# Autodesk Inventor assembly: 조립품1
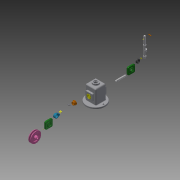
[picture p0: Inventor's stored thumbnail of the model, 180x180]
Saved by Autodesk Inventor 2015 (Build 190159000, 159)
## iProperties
Created: 2021-08
Part Number: 조립품1
Document SubType Name: Assembly
Designer: 104658
Author: 104658
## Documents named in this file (16)
- C:\Users\104658\Desktop\710806V1022\조립품1.iam
- C:\Users\104658\Desktop\710806V1022\V벨트풀리.ipt
- C:\Users\104658\Desktop\710806V1022\고정핀 1.2x8.ipt
- C:\Users\104658\Desktop\710806V1022\뒤커버.ipt
- C:\Users\104658\Desktop\710806V1022\링크.ipt
- C:\Users\104658\Desktop\710806V1022\멈춤나사 M3x8.ipt
- C:\Users\104658\Desktop\710806V1022\베어링 12x32x10.ipt
- C:\Users\104658\Desktop\710806V1022\볼트 M4.ipt
- C:\Users\104658\Desktop\710806V1022\부시.ipt
- C:\Users\104658\Desktop\710806V1022\부품1.ipt
- C:\Users\104658\Desktop\710806V1022\슬라이드.ipt
- C:\Users\104658\Desktop\710806V1022\앞커버.ipt
- C:\Users\104658\Desktop\710806V1022\오일 실 12 25 7.ipt
- C:\Users\104658\Desktop\710806V1022\키 4x4x10.ipt
- C:\Users\104658\Desktop\710806V1022\편심축.ipt
- C:\Users\104658\Desktop\710806V1022\핀 5x18.ipt
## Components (3 placed, 3 different names)
1. V벨트풀리:1
2. 고정핀 1.2x8:1
3. 핀 5x18:1
